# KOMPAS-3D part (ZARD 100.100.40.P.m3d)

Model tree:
1. Операция без истории:1
2. Операция без истории:2
3. Операция без истории:3
4. Операция без истории:4
5. Операция без истории:5
6. Операция без истории:6
7. Операция без истории:7
8. Операция без истории:8
9. Операция без истории:9
10. Операция без истории:10
11. Операция без истории:11
12. Операция без истории:12
13. Операция без истории:13
14. Операция без истории:14
15. Операция без истории:15
16. Операция без истории:16
17. Операция без истории:17
18. Операция без истории:18
19. Операция без истории:19
20. Операция без истории:20
21. Операция без истории:21
22. Операция без истории:22
23. Операция без истории:23
24. Операция без истории:24
25. Операция без истории:25
26. Операция без истории:26
27. Операция без истории:27
28. Операция без истории:28
29. Операция без истории:29
30. Операция без истории:30
31. Операция без истории:31
32. Операция без истории:32
33. Операция без истории:33
34. Операция без истории:34
35. Операция без истории:35
36. Операция без истории:36
37. Операция без истории:37
38. Операция без истории:38
39. Операция без истории:39
40. Операция без истории:40
41. Операция без истории:41
42. Операция без истории:42
43. Операция без истории:43
44. Операция без истории:44
45. Операция без истории:45
46. Операция без истории:46
47. Операция без истории:47
48. Операция без истории:48
49. Операция без истории:49
50. Операция без истории:50
51. Операция без истории:51
52. Операция без истории:52
53. Операция без истории:53
54. Операция без истории:54
55. Операция без истории:55
56. Операция без истории:56
57. Операция без истории:57
58. Операция без истории:58
59. Операция без истории:59
60. Операция без истории:60
61. Операция без истории:61
62. Операция без истории:62
63. Операция без истории:63
64. Операция без истории:64
65. Операция без истории:65
66. Операция без истории:66
67. Операция без истории:67
68. Операция без истории:68
69. Операция без истории:69
70. Операция без истории:70
71. Операция без истории:71
72. Операция без истории:72
73. Операция без истории:73
74. Операция без истории:74
75. Операция без истории:75
76. Операция без истории:76
77. Операция без истории:77
78. Операция без истории:78
79. Операция без истории:79
80. Операция без истории:80
81. Операция без истории:81
82. Операция без истории:82
83. Операция без истории:83
84. Операция без истории:84
85. Операция без истории:85
86. Операция без истории:86
87. Операция без истории:87
88. Операция без истории:88
89. Операция без истории:89
90. Операция без истории:90
91. Операция без истории:91
92. Операция без истории:92
93. Операция без истории:93
94. Операция без истории:94
95. Операция без истории:95
96. Операция без истории:96
97. Операция без истории:97
98. Операция без истории:98
99. Операция без истории:99
100. Операция без истории:100
101. Операция без истории:101
102. Поверхность без истории:1

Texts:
  ЗАРД 100.100.40-ХХ.Р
